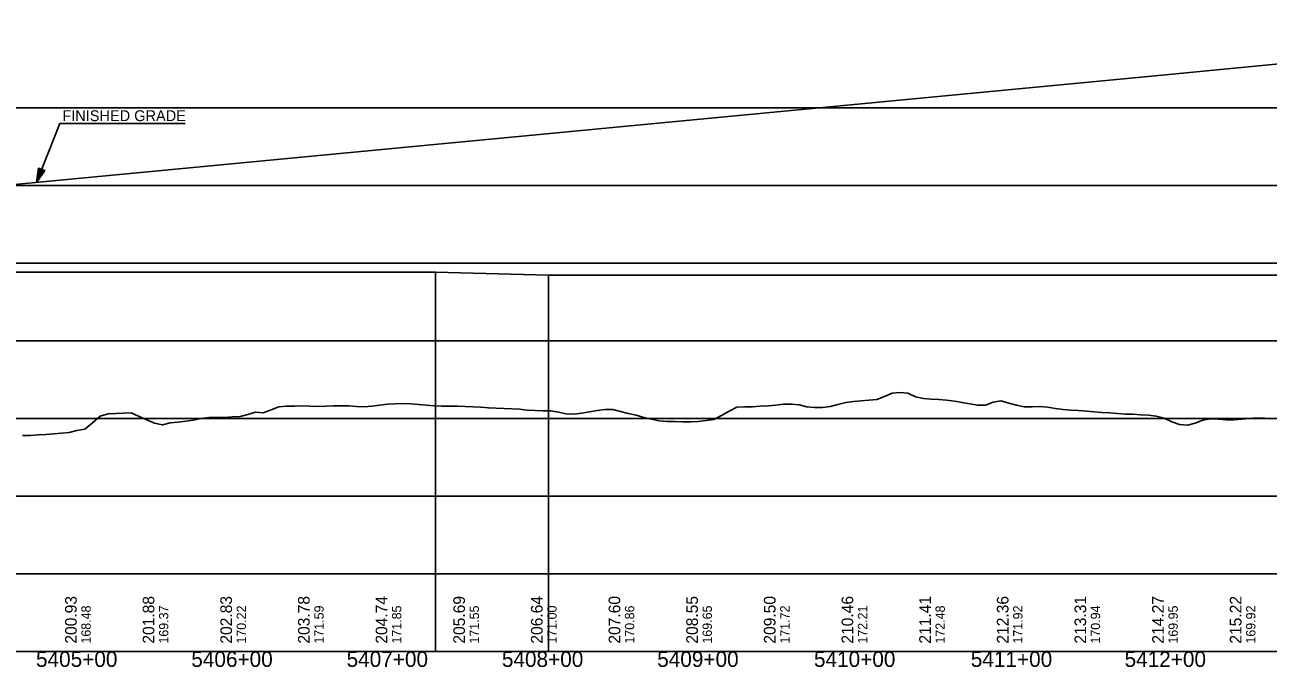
# Model space of a CAD drawing. Extents: x 69 to 2003113, y 512 to 837401.
# Drawn here: x 1884403 to 1885203, y 775979 to 776393 of the extents above; entities that cross this region are included whole.
import ezdxf

# ---------------------------------------------------------------- set-up
doc = ezdxf.new("R2010")
doc.units = 0
for name, color, linetype in [('BR_AUTO DIMENSION', 7, 'Continuous'), ('BR_BORDER LINES', 7, 'Continuous'), ('BR_CONCRETE', 7, 'Continuous'), ('BR_GRID LINES', 7, 'Continuous'), ('BR_TEXT', 7, 'Continuous'), ('RD_HC_Points', 7, 'Continuous'), ('RD_PD_ALT1_TrvlWay', 7, 'Continuous'), ('RD_SHT_ID', 7, 'Continuous')]:
    doc.layers.add(name, color=color, linetype=linetype)

msp = doc.modelspace()

# ---------------------------------------------------------------- linework, layer by layer
at = {"layer": 'BR_AUTO DIMENSION'}
for p, q in [((1883686.1, 776339.14), (1888825.1, 776339.14)), ((1883686.1, 776289.14), (1888825.1, 776289.14)), ((1883686.1, 776239.14), (1888825.1, 776239.14)), ((1883778.33, 776233.39), (1884666.93, 776233.39)), ((1884666.93, 776233.39), (1884666.93, 775989.14)), ((1884739.76, 776231.44), (1884666.93, 776233.39)), ((1884739.76, 776231.44), (1884739.76, 775989.14)), ((1884739.76, 776231.44), (1885521.42, 776231.44)), ((1883686.1, 776189.14), (1888825.1, 776189.14)), ((1883686.1, 776139.14), (1888825.1, 776139.14)), ((1883686.1, 776089.14), (1888825.1, 776089.14)), ((1883686.1, 776039.14), (1888825.1, 776039.14)), ((1883636.94, 775989.14), (1888825.1, 775989.14))]:
    msp.add_line(p, q, dxfattribs=at)
at = {"layer": 'BR_BORDER LINES'}
msp.add_line((1883686.1, 775989.14), (1889486.1, 775989.14), dxfattribs=at)
at = {"layer": 'BR_GRID LINES'}
for p, q in [((1885136.94, 776360.48), (1885474.32, 776392.63)), ((1884189.13, 776270.15), (1885136.94, 776360.48))]:
    msp.add_line(p, q, dxfattribs=at)
at = {"layer": 'BR_TEXT'}
for points in [[(1884686.1, 776146.91), (1884691.1, 776146.68), (1884696.1, 776146.36), (1884701.1, 776146.05), (1884706.1, 776145.74), (1884711.1, 776145.46), (1884716.1, 776145.27), (1884721.1, 776145.08), (1884726.1, 776144.46), (1884731.1, 776144.23), (1884736.1, 776144.14), (1884741.1, 776144.14), (1884746.1, 776143.19), (1884751.1, 776142.09), (1884756.1, 776141.85), (1884761.1, 776142.6), (1884766.1, 776143.47), (1884771.1, 776144.38), (1884776.1, 776144.92), (1884781.1, 776144.88), (1884786.1, 776143.66), (1884791.1, 776142.44), (1884796.1, 776141.19), (1884801.1, 776139.79), (1884806.1, 776138.66), (1884811.1, 776137.61), (1884816.1, 776137.21), (1884821.1, 776137.09), (1884826.1, 776136.97), (1884831.1, 776136.98), (1884836.1, 776137.3), (1884841.1, 776137.84), (1884846.1, 776138.41), (1884851.1, 776141.07), (1884856.1, 776143.89), (1884861.1, 776146.39), (1884866.1, 776146.61), (1884871.1, 776146.69), (1884876.1, 776147), (1884881.1, 776147.3), (1884886.1, 776147.61), (1884891.1, 776148.4), (1884896.1, 776148.45), (1884901.1, 776147.88), (1884906.1, 776146.72), (1884911.1, 776146.19), (1884916.1, 776146.2), (1884921.1, 776146.89), (1884926.1, 776148.22), (1884931.1, 776149.34), (1884936.1, 776150.11), (1884941.1, 776150.52), (1884946.1, 776150.9), (1884951.1, 776151.34), (1884956.1, 776153.38), (1884961.1, 776155.41), (1884966.1, 776155.86), (1884971.1, 776155.38), (1884976.1, 776152.98), (1884981.1, 776152.11), (1884986.1, 776151.6), (1884991.1, 776151.34), (1884996.1, 776151.03), (1885001.1, 776150.28), (1885006.1, 776149.35), (1885011.1, 776148.5), (1885016.1, 776147.64), (1885021.1, 776147.68), (1885026.1, 776149.7), (1885031.1, 776150.51), (1885036.1, 776148.95), (1885041.1, 776147.66), (1885046.1, 776146.72), (1885051.1, 776146.71), (1885056.1, 776146.93), (1885061.1, 776146.36), (1885066.1, 776145.56), (1885071.1, 776144.94), (1885076.1, 776144.44), (1885081.1, 776144.18), (1885086.1, 776143.94), (1885091.1, 776143.45), (1885096.1, 776143.06), (1885101.1, 776142.72), (1885106.1, 776142.32), (1885111.1, 776141.95), (1885116.1, 776141.84), (1885121.1, 776141.46), (1885126.1, 776141.35), (1885131.1, 776140.64), (1885136.1, 776139.25), (1885141.1, 776137.01), (1885146.1, 776135.3), (1885151.1, 776134.75), (1885156.1, 776136.1), (1885161.1, 776138.14), (1885166.1, 776138.89), (1885171.1, 776138.64), (1885176.1, 776138.37), (1885181.1, 776138.27), (1885186.1, 776138.69)], [(1884401.1, 776128.11), (1884406.1, 776128.11), (1884411.1, 776128.52), (1884416.1, 776128.92), (1884421.1, 776129.32), (1884426.1, 776129.72), (1884431.1, 776130.12), (1884436.1, 776131.4), (1884441.1, 776132.33), (1884446.1, 776136.26), (1884451.1, 776140.71), (1884456.1, 776142.14), (1884461.1, 776142.34), (1884466.1, 776142.65), (1884471.1, 776142.85), (1884476.1, 776140.46), (1884481.1, 776138.27), (1884486.1, 776136.22), (1884491.1, 776134.99), (1884496.1, 776136.38), (1884501.1, 776136.77), (1884506.1, 776137.39), (1884511.1, 776138.14), (1884516.1, 776139.22), (1884521.1, 776139.67), (1884526.1, 776139.95), (1884531.1, 776139.87), (1884536.1, 776140.21), (1884541.1, 776140.51), (1884546.1, 776141.81), (1884551.1, 776143.13), (1884556.1, 776142.81), (1884561.1, 776144.71), (1884566.1, 776146.73), (1884571.1, 776147.02), (1884576.1, 776147.13), (1884581.1, 776147.22), (1884586.1, 776147.11), (1884591.1, 776146.96), (1884596.1, 776146.99), (1884601.1, 776147.19), (1884606.1, 776147.27), (1884611.1, 776147.34), (1884616.1, 776146.95), (1884621.1, 776146.59), (1884626.1, 776147.06), (1884631.1, 776147.71), (1884636.1, 776148.32), (1884641.1, 776148.67), (1884646.1, 776148.81), (1884651.1, 776148.62), (1884656.1, 776148.22), (1884661.1, 776147.8), (1884666.1, 776147.39), (1884671.1, 776147.13), (1884676.1, 776147.11), (1884681.1, 776147.09), (1884686.1, 776146.91)], [(1885186.1, 776138.69), (1885191.1, 776139.17), (1885196.1, 776139.62), (1885201.1, 776139.43), (1885206.1, 776138.9)]]:
    msp.add_lwpolyline(points, dxfattribs=at)
at = {"layer": 'RD_PD_ALT1_TrvlWay'}
for p, q in [((1884410.08, 776291.21), (1884425.04, 776329.17)), ((1884425.04, 776329.17), (1884505.82, 776329.17)), ((1884410.08, 776291.21), (1884411.29, 776300.41)), ((1884410.08, 776291.21), (1884411.29, 776300.41)), ((1884413.38, 776299.58), (1884410.08, 776291.21)), ((1884413.38, 776299.58), (1884410.08, 776291.21)), ((1884410.08, 776291.21), (1884415.47, 776298.76)), ((1884410.08, 776291.21), (1884415.47, 776298.76)), ((1884411.29, 776300.41), (1884415.47, 776298.76)), ((1884411.29, 776300.41), (1884415.47, 776298.76))]:
    msp.add_line(p, q, dxfattribs=at)
for points in [[(1884413.28, 776299.5), (1884410.21, 776291.71), (1884413.25, 776299.58), (1884410.28, 776292.1), (1884413.15, 776299.57), (1884410.31, 776292.37), (1884413.04, 776299.6), (1884410.34, 776292.7), (1884412.96, 776299.65), (1884410.41, 776293.19), (1884412.84, 776299.71), (1884410.5, 776293.71), (1884412.72, 776299.72), (1884410.55, 776294.11), (1884412.64, 776299.77), (1884410.61, 776294.57), (1884412.54, 776299.75), (1884410.67, 776294.97), (1884412.48, 776299.86), (1884410.71, 776295.31), (1884412.34, 776299.87), (1884410.76, 776295.81), (1884412.25, 776299.93), (1884410.88, 776296.41), (1884412.15, 776299.99), (1884410.88, 776296.82), (1884412.05, 776300.03), (1884410.97, 776297.45), (1884411.93, 776300.04), (1884411.07, 776297.95), (1884411.83, 776300.13), (1884411.12, 776298.39), (1884411.73, 776300.13), (1884411.16, 776298.8), (1884411.64, 776300.23), (1884411.23, 776299.29), (1884411.53, 776300.19), (1884411.31, 776299.84), (1884411.41, 776300.2)], [(1884413.28, 776299.5), (1884410.21, 776291.71), (1884413.25, 776299.58), (1884410.28, 776292.1), (1884413.15, 776299.57), (1884410.31, 776292.37), (1884413.04, 776299.6), (1884410.34, 776292.7), (1884412.96, 776299.65), (1884410.41, 776293.19), (1884412.84, 776299.71), (1884410.5, 776293.71), (1884412.72, 776299.72), (1884410.55, 776294.11), (1884412.64, 776299.77), (1884410.61, 776294.57), (1884412.54, 776299.75), (1884410.67, 776294.97), (1884412.48, 776299.86), (1884410.71, 776295.31), (1884412.34, 776299.87), (1884410.76, 776295.81), (1884412.25, 776299.93), (1884410.88, 776296.41), (1884412.15, 776299.99), (1884410.88, 776296.82), (1884412.05, 776300.03), (1884410.97, 776297.45), (1884411.93, 776300.04), (1884411.07, 776297.95), (1884411.83, 776300.13), (1884411.12, 776298.39), (1884411.73, 776300.13), (1884411.16, 776298.8), (1884411.64, 776300.23), (1884411.23, 776299.29), (1884411.53, 776300.19), (1884411.31, 776299.84), (1884411.41, 776300.2)], [(1884410.35, 776291.73), (1884413.4, 776299.45), (1884410.52, 776291.99), (1884413.5, 776299.41), (1884410.67, 776292.22), (1884413.59, 776299.42), (1884410.85, 776292.43), (1884413.65, 776299.38), (1884411.05, 776292.69), (1884413.74, 776299.36), (1884411.23, 776292.94), (1884413.81, 776299.33), (1884411.45, 776293.24), (1884413.91, 776299.32), (1884411.69, 776293.6), (1884414.02, 776299.25), (1884411.9, 776293.92), (1884414.1, 776299.26), (1884412.13, 776294.25), (1884414.18, 776299.21), (1884412.37, 776294.56), (1884414.27, 776299.17), (1884412.61, 776294.9), (1884414.32, 776299.09), (1884412.93, 776295.36), (1884414.42, 776299.09), (1884413.16, 776295.65), (1884414.5, 776299.1), (1884413.45, 776296.03), (1884414.57, 776299.03), (1884413.69, 776296.44), (1884414.67, 776298.97), (1884413.91, 776296.75), (1884414.75, 776298.88), (1884414.17, 776297.03), (1884414.82, 776298.85), (1884414.45, 776297.5), (1884414.97, 776298.87), (1884414.64, 776297.77), (1884415.11, 776298.82), (1884414.82, 776297.93), (1884415.22, 776298.68), (1884415.34, 776298.73), (1884415.18, 776298.69)], [(1884410.35, 776291.73), (1884413.4, 776299.45), (1884410.52, 776291.99), (1884413.5, 776299.41), (1884410.67, 776292.22), (1884413.59, 776299.42), (1884410.85, 776292.43), (1884413.65, 776299.38), (1884411.05, 776292.69), (1884413.74, 776299.36), (1884411.23, 776292.94), (1884413.81, 776299.33), (1884411.45, 776293.24), (1884413.91, 776299.32), (1884411.69, 776293.6), (1884414.02, 776299.25), (1884411.9, 776293.92), (1884414.1, 776299.26), (1884412.13, 776294.25), (1884414.18, 776299.21), (1884412.37, 776294.56), (1884414.27, 776299.17), (1884412.61, 776294.9), (1884414.32, 776299.09), (1884412.93, 776295.36), (1884414.42, 776299.09), (1884413.16, 776295.65), (1884414.5, 776299.1), (1884413.45, 776296.03), (1884414.57, 776299.03), (1884413.69, 776296.44), (1884414.67, 776298.97), (1884413.91, 776296.75), (1884414.75, 776298.88), (1884414.17, 776297.03), (1884414.82, 776298.85), (1884414.45, 776297.5), (1884414.97, 776298.87), (1884414.64, 776297.77), (1884415.11, 776298.82), (1884414.82, 776297.93), (1884415.22, 776298.68), (1884415.34, 776298.73), (1884415.18, 776298.69)]]:
    msp.add_lwpolyline(points, dxfattribs=at)

# ---------------------------------------------------------------- texts
at = {"layer": 'BR_CONCRETE'}
for s, p in [('168.48', (1884444.94, 775994.14)), ('169.37', (1884494.94, 775994.14)), ('170.22', (1884544.94, 775994.14)), ('171.59', (1884594.94, 775994.14)), ('171.85', (1884644.94, 775994.14)), ('171.55', (1884694.94, 775994.14)), ('171.00', (1884744.94, 775994.14)), ('170.86', (1884794.94, 775994.14)), ('169.65', (1884844.94, 775994.14)), ('171.72', (1884894.94, 775994.14)), ('172.21', (1884944.94, 775994.14)), ('172.48', (1884994.94, 775994.14)), ('171.92', (1885044.94, 775994.14)), ('170.94', (1885094.94, 775994.14)), ('169.95', (1885144.94, 775994.14)), ('169.92', (1885194.94, 775994.14))]:
    msp.add_text(s, height=6, rotation=90, dxfattribs=at).set_placement(p)
at = {"layer": 'RD_HC_Points'}
for s, p in [('200.93', (1884435.94, 775994.14)), ('201.88', (1884485.94, 775994.14)), ('202.83', (1884535.94, 775994.14)), ('203.78', (1884585.94, 775994.14)), ('204.74', (1884635.94, 775994.14)), ('205.69', (1884685.94, 775994.14)), ('206.64', (1884735.94, 775994.14)), ('207.60', (1884785.94, 775994.14)), ('208.55', (1884835.94, 775994.14)), ('209.50', (1884885.94, 775994.14)), ('210.46', (1884935.94, 775994.14)), ('211.41', (1884985.94, 775994.14)), ('212.36', (1885035.94, 775994.14)), ('213.31', (1885085.94, 775994.14)), ('214.27', (1885135.94, 775994.14)), ('215.22', (1885185.94, 775994.14))]:
    msp.add_text(s, height=7.5, rotation=90, dxfattribs=at).set_placement(p)
at = {"layer": 'RD_PD_ALT1_TrvlWay'}
msp.add_text('FINISHED GRADE', height=7, dxfattribs=at).set_placement((1884426.68, 776330.63))
at = {"layer": 'RD_SHT_ID'}
for s, p in [('5405+00', (1884409.72, 775979.14)), ('5406+00', (1884509.72, 775979.14)), ('5407+00', (1884609.72, 775979.14)), ('5408+00', (1884709.72, 775979.14)), ('5409+00', (1884809.72, 775979.14)), ('5410+00', (1884910.68, 775979.14)), ('5411+00', (1885011.65, 775979.14)), ('5412+00', (1885110.68, 775979.14))]:
    msp.add_text(s, height=10, dxfattribs=at).set_placement(p)

doc.saveas('drawing.dxf')
